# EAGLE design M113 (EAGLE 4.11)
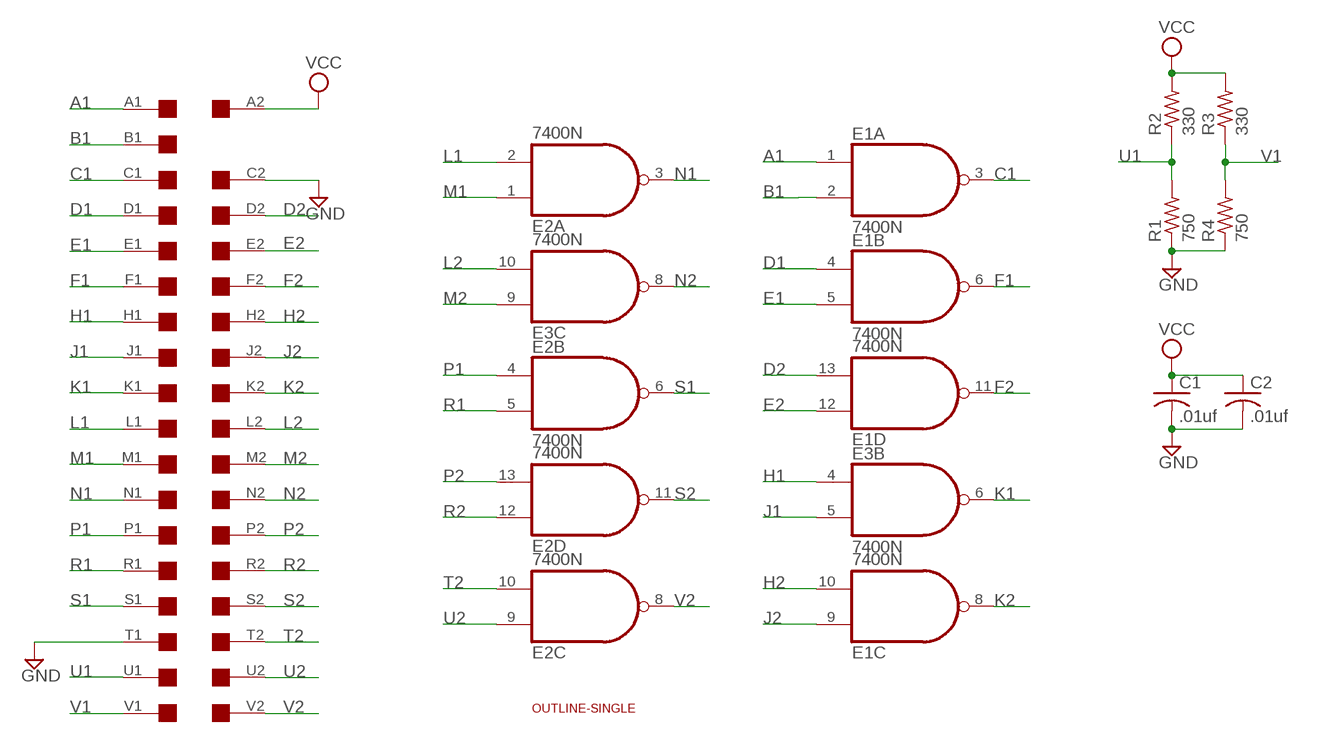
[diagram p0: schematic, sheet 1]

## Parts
C1  .01uf  C-US050-025X075  [C050-025X075]
C2  .01uf  C-US050-025X075  [C050-025X075]
E1  7400N  [DIL14]
E2  7400N  [DIL14]
E3  7400N  [DIL14]
R1  750  R-US_0207/10  [0207/10]
R2  330  R-US_0207/10  [0207/10]
R3  330  R-US_0207/10  [0207/10]
R4  750  R-US_0207/10  [0207/10]
U$1  SINGLE  [EDGE-CON2]
U$2  OUTLINE-SINGLE  [SINGLE]

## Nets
A1: E1.1(A:I0) U$1.A1
B1: E1.2(A:I1) U$1.B1
C1: E1.3(A:O) U$1.C1
D1: E1.4(B:I0) U$1.D1
D2: E1.13(D:I1) U$1.D2
E1: E1.5(B:I1) U$1.E1
E2: E1.12(D:I0) U$1.E2
F1: E1.6(B:O) U$1.F1
F2: E1.11(D:O) U$1.F2
GND: C1.2 C2.2 R1.1 R4.1 U$1.C2 U$1.T1
H1: E3.4(B:I0) U$1.H1
H2: E1.10(C:I1) U$1.H2
J1: E3.5(B:I1) U$1.J1
J2: E1.9(C:I0) U$1.J2
K1: E3.6(B:O) U$1.K1
K2: E1.8(C:O) U$1.K2
L1: E2.2(A:I1) U$1.L1
L2: E3.10(C:I1) U$1.L2
M1: E2.1(A:I0) U$1.M1
M2: E3.9(C:I0) U$1.M2
N1: E2.3(A:O) U$1.N1
N2: E3.8(C:O) U$1.N2
P1: E2.4(B:I0) U$1.P1
P2: E2.13(D:I1) U$1.P2
R1: E2.5(B:I1) U$1.R1
R2: E2.12(D:I0) U$1.R2
S1: E2.6(B:O) U$1.S1
S2: E2.11(D:O) U$1.S2
T2: E2.10(C:I1) U$1.T2
U1: R1.2 R2.1 U$1.U1
U2: E2.9(C:I0) U$1.U2
V1: R3.1 R4.2 U$1.V1
V2: E2.8(C:O) U$1.V2
VCC: C1.1 C2.1 R2.2 R3.2 U$1.A2
Unconnected: E3.1(A:I0) E3.2(A:I1) E3.3(A:O) E3.11(D:O) E3.12(D:I0) E3.13(D:I1) U$1.B2

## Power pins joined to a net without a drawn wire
GND: E1.7(P:GND) E2.7(P:GND) E3.7(P:GND)
VCC: E1.14(P:VCC) E2.14(P:VCC) E3.14(P:VCC)

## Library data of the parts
C1 C2 = rcl:C-US: CAPACITOR, American symbol
E1-E3 = 74xx-us:74*00: Quad 2-input NAND gate
R1-R4 = rcl:R-US_: RESISTOR, American symbol
U$1 = dec-con:SINGLE: Single-Height DEC board
U$2 = dec-con:OUTLINE-*: Board outlines for DEC boards.

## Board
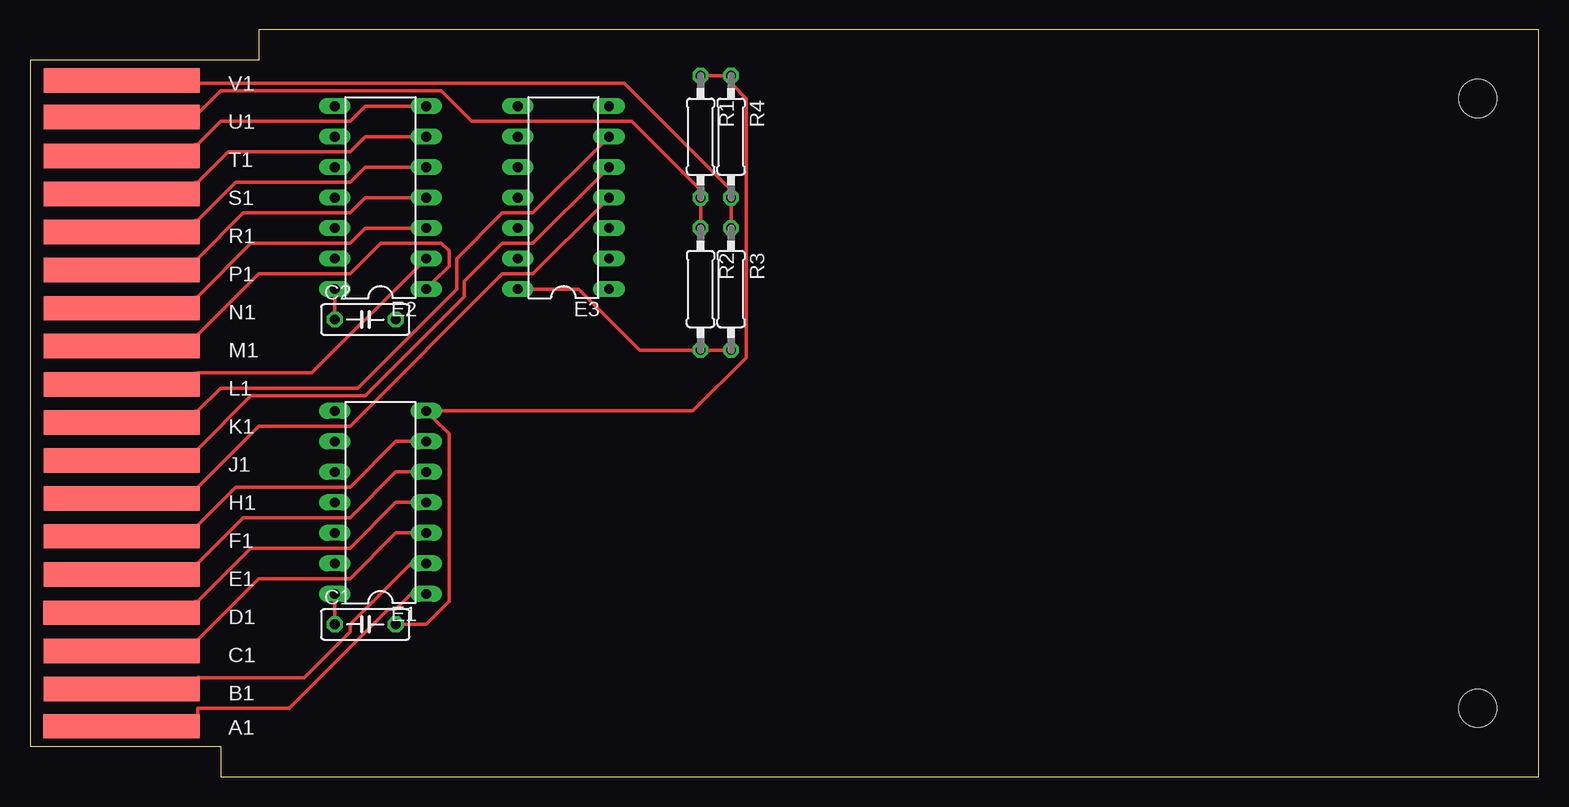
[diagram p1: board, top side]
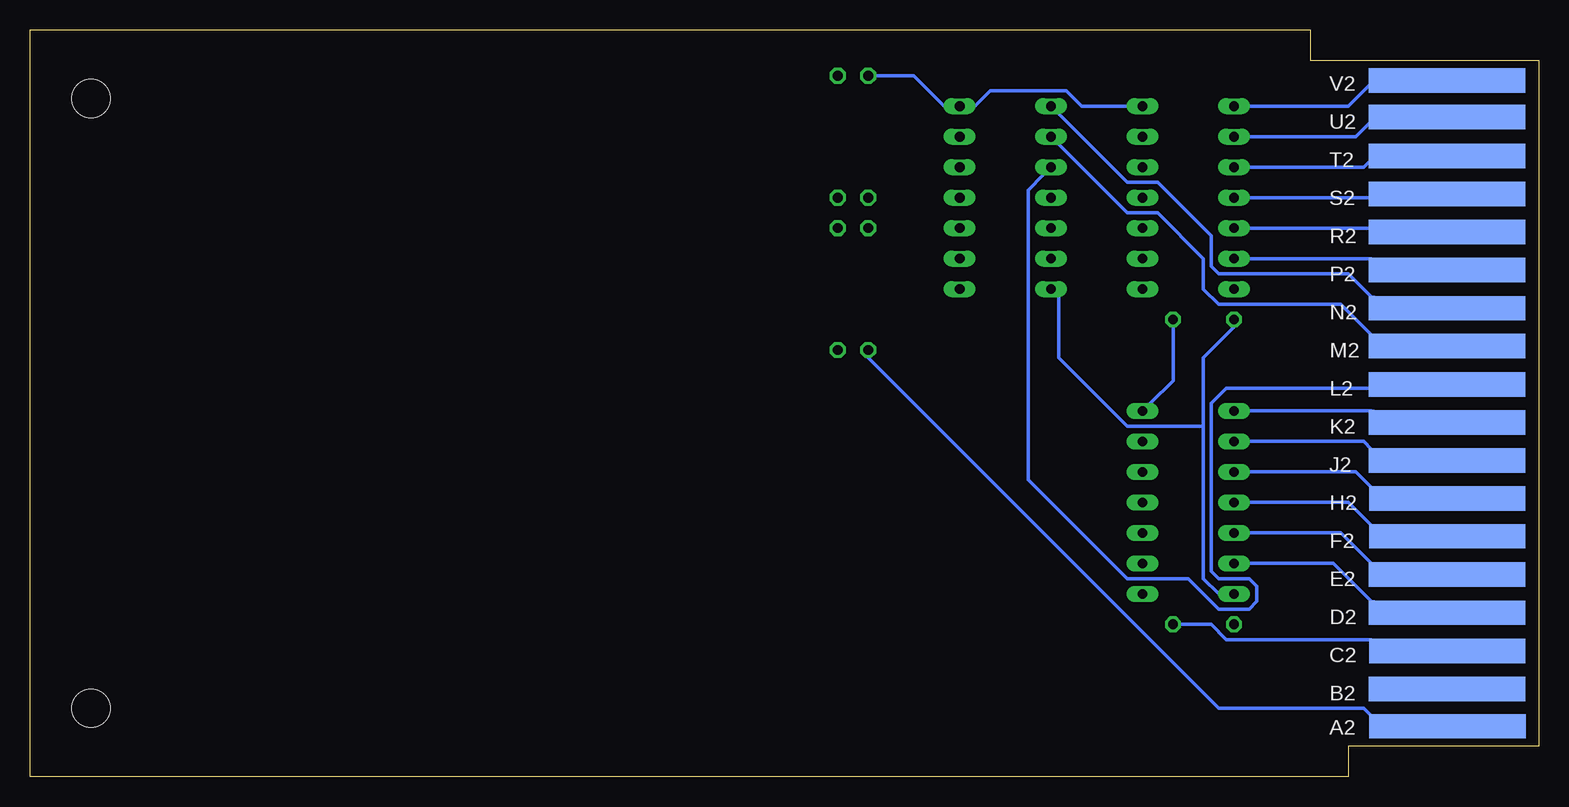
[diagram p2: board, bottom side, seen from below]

Size 125.73 x 62.23 mm. Coordinates in mm from the lower left corner, seen from the top.
Copper layers (1*16): Top 0.035mm / dielectric 1.5mm / Bottom 0.035mm
Design rules "10mils": minimum track width 12mil, minimum drill 28mil, track to track 10mil, track to pad 10mil, pad to pad 10mil, via to via 10mil, smd to smd 10mil, copper to edge 25mil, drill to drill 10mil, minimum pad ring 10mil, minimum via ring 8mil, stop-mask expansion 0mil, vias tented up to drill 0mil, thermal gap 10mil

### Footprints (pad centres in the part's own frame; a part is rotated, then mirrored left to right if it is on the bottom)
C050-025X075 = drill 0.813 octagon: 1 -2.54,0; 2 2.54,0
DIL14 = drill 0.813 long: 1 -7.62,-3.81; 2 -5.08,-3.81; 3 -2.54,-3.81; 4 0,-3.81; 5 2.54,-3.81; 6 5.08,-3.81; 7 7.62,-3.81; 8 7.62,3.81; 9 5.08,3.81; 10 2.54,3.81; 11 0,3.81; 12 -2.54,3.81; 13 -5.08,3.81; 14 -7.62,3.81
0207/10 = drill 0.813 octagon: 1 -5.08,0; 2 5.08,0
EDGE-CON2 = smd 13.017 x 2.032: A1 7.633,4.207; B1 7.639,7.327; C1 7.636,10.489; D1 7.633,13.665; E1 7.642,16.84; F1 7.642,20.041; H1 7.642,23.19; J1 7.642,26.34; K1 7.642,29.515; L1 7.642,32.69; M1 7.642,35.89; N1 7.642,39.04; P1 7.642,42.24; R1 7.642,45.39; S1 7.642,48.565; T1 7.642,51.74; U1 7.642,54.966; V1 7.642,58.026 | smd 13.017 x 2.032 bottom: A2 7.614,4.207; B2 7.642,7.328; C2 7.617,10.49; D2 7.642,13.665; E2 7.642,16.84; F2 7.617,20.041; H2 7.617,23.19; J2 7.642,26.34; K2 7.642,29.515; L2 7.642,32.69; M2 7.642,35.89; N2 7.642,39.04; P2 7.642,42.24; R2 7.642,45.39; S2 7.642,48.565; T2 7.642,51.74; U2 7.642,54.966; V2 7.642,58.026
SINGLE = hole 3.175: 120.65,56.515; 120.65,5.715

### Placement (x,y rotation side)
C1  27.94,12.7 0 top
C2  27.94,38.1 0 top
E1  29.21,22.86 90 top
E2  29.21,48.26 90 top
E3  44.45,48.26 90 top
R1  55.88,53.34 270 top
R2  55.88,40.64 270 top
R3  58.42,40.64 270 top
R4  58.42,53.34 270 top
U$1  0,0 0 top
U$2  0,0 0 top

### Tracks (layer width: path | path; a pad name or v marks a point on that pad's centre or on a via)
A1
  Top 0.305: E1.1 31.75,15.24 30.48,13.97 29.85,13.97 21.59,5.71 13.97,5.71 13.97,5.08 U$1.A1
B1
  Top 0.305: E1.2 31.75,17.78 26.67,12.7 26.67,12.06 22.86,8.26 13.97,8.26 U$1.B1
C1
  Top 0.305: E1.3 31.75,20.32 30.48,20.32 26.67,16.51 19.05,16.51 13.97,11.43 U$1.C1
D1
  Top 0.305: E1.4 31.75,22.86 30.48,22.86 26.67,19.05 18.42,19.05 13.97,14.61 U$1.D1
D2
  Bottom 0.305: E1.13 24.13,17.78 17.15,17.78 13.97,14.61 U$1.D2
E1
  Top 0.305: E1.5 31.75,25.4 30.48,25.4 26.67,21.59 17.78,21.59 13.97,17.78 U$1.E1
E2
  Bottom 0.305: E1.12 24.13,20.32 16.51,20.32 13.97,17.78 U$1.E2
F1
  Top 0.305: E1.6 31.75,27.94 30.48,27.94 26.67,24.13 17.15,24.13 13.97,20.95 U$1.F1
F2
  Bottom 0.305: E1.11 24.13,22.86 15.88,22.86 13.97,20.95 U$1.F2
GND
  Top 0.305: C1.2 31.12,12.7 33.02,12.7 34.93,14.61 34.93,28.57 33.66,29.84 E1.7 34.29,30.48 55.25,30.48 59.69,34.92 59.69,56.52 58.42,57.78 R4.1 57.79,58.42 56.52,58.42 R1.1 | E2.7 31.75,55.88 27.94,55.88 26.67,54.61 15.88,54.61 13.97,52.7 U$1.T1
  Bottom 0.305: C2.2 30.48,37.47 30.48,33.02 32.39,31.11 E1.7 | C1.2 29.85,12.7 27.31,12.7 26.04,11.43 13.97,11.43 U$1.C2 | E2.7 34.29,55.88 38.1,55.88 39.37,57.15 45.72,57.15 46.99,55.88 E3.7 49.53,55.88 52.07,58.42 55.25,58.42 R1.1
H1
  Top 0.305: E3.4 47.63,47.62 41.91,41.91 39.37,41.91 26.67,29.21 19.05,29.21 13.97,24.13 U$1.H1
H2
  Bottom 0.305: E1.10 24.13,25.4 15.24,25.4 13.97,24.13 U$1.H2
J1
  Top 0.305: E3.5 47.63,50.16 41.91,44.45 39.37,44.45 36.2,41.27 36.2,40.01 27.94,31.75 18.42,31.75 13.97,27.3 U$1.J1
J2
  Bottom 0.305: E1.9 24.13,27.94 14.61,27.94 13.97,27.3 U$1.J2
K1
  Top 0.305: E3.6 47.63,52.7 41.91,46.99 39.37,46.99 35.56,43.18 35.56,40.64 27.31,32.38 15.88,32.38 13.97,30.48 U$1.K1
K2
  Bottom 0.305: E1.8 24.13,30.48 13.97,30.48 U$1.K2
L1
  Top 0.305: E2.2 32.39,42.55 23.5,33.66 13.97,33.66 U$1.L1
L2
  Bottom 0.305: E3.10 41.28,50.16 42.55,48.9 42.55,24.77 34.29,16.51 29.21,16.51 26.67,13.97 24.13,13.97 23.5,14.61 23.5,15.88 24.13,16.51 26.67,16.51 27.31,17.14 27.31,31.11 26.04,32.38 13.97,32.38 U$1.L2
M1
  Top 0.305: E2.1 33.66,41.27 34.93,42.55 34.93,43.81 34.29,44.45 29.21,44.45 26.67,41.91 19.05,41.91 13.97,36.83 U$1.M1
M2
  Bottom 0.305: E3.9 40.01,52.7 34.29,46.99 31.75,46.99 27.94,43.18 27.94,40.64 26.67,39.37 16.51,39.37 13.97,36.83 U$1.M2
N1
  Top 0.305: E2.3 31.75,45.72 27.94,45.72 26.67,44.45 18.42,44.45 13.97,40.01 U$1.N1
N2
  Bottom 0.305: E3.8 40.01,55.24 34.29,49.53 31.75,49.53 27.31,45.09 27.31,42.55 26.67,41.91 15.88,41.91 13.97,40.01 U$1.N2
P1
  Top 0.305: E2.4 31.75,48.26 27.94,48.26 26.67,46.99 17.78,46.99 13.97,43.18 U$1.P1
P2
  Bottom 0.305: E2.13 24.13,43.18 13.97,43.18 U$1.P2
R1
  Top 0.305: E2.5 31.75,50.8 27.94,50.8 26.67,49.53 17.15,49.53 13.97,46.35 U$1.R1
R2
  Bottom 0.305: E2.12 24.13,45.72 13.97,45.72 U$1.R2
S1
  Top 0.305: E2.6 31.75,53.34 27.94,53.34 26.67,52.07 16.51,52.07 13.97,49.53 U$1.S1
S2
  Bottom 0.305: E2.11 24.13,48.26 13.97,48.26 U$1.S2
T2
  Bottom 0.305: E2.10 24.13,50.8 14.61,50.8 13.97,51.44 U$1.T2
U1
  Top 0.305: R2.1 55.88,46.35 55.88,47.62 R1.2 55.88,48.9 50.17,54.61 36.83,54.61 34.29,57.15 15.88,57.15 13.97,55.24 U$1.U1
U2
  Bottom 0.305: E2.9 24.13,53.34 15.24,53.34 13.97,54.61 U$1.U2
V1
  Top 0.305: R3.1 58.42,46.35 58.42,47.62 R4.2 58.42,48.9 49.53,57.78 13.97,57.78 U$1.V1
V2
  Bottom 0.305: E2.8 24.13,55.88 15.88,55.88 13.97,57.78 U$1.V2
VCC
  Top 0.305: R3.2 57.79,35.56 56.52,35.56 R2.2 55.25,35.56 50.8,35.56 45.72,40.64 41.91,40.64 E3.14 | C1.1 25.4,13.34 25.4,14.61 E1.14 | C2.1 25.4,38.73 25.4,40.01 E2.14
  Bottom 0.305: 27.94,29.21 27.94,34.92 25.4,37.47 C2.1 | 27.94,29.21 27.94,16.51 26.67,15.24 E1.14 | 27.94,29.21 34.29,29.21 40.01,34.92 40.01,40.01 E3.14 | R2.2 55.88,34.92 26.67,5.71 14.61,5.71 13.97,5.08 U$1.A2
